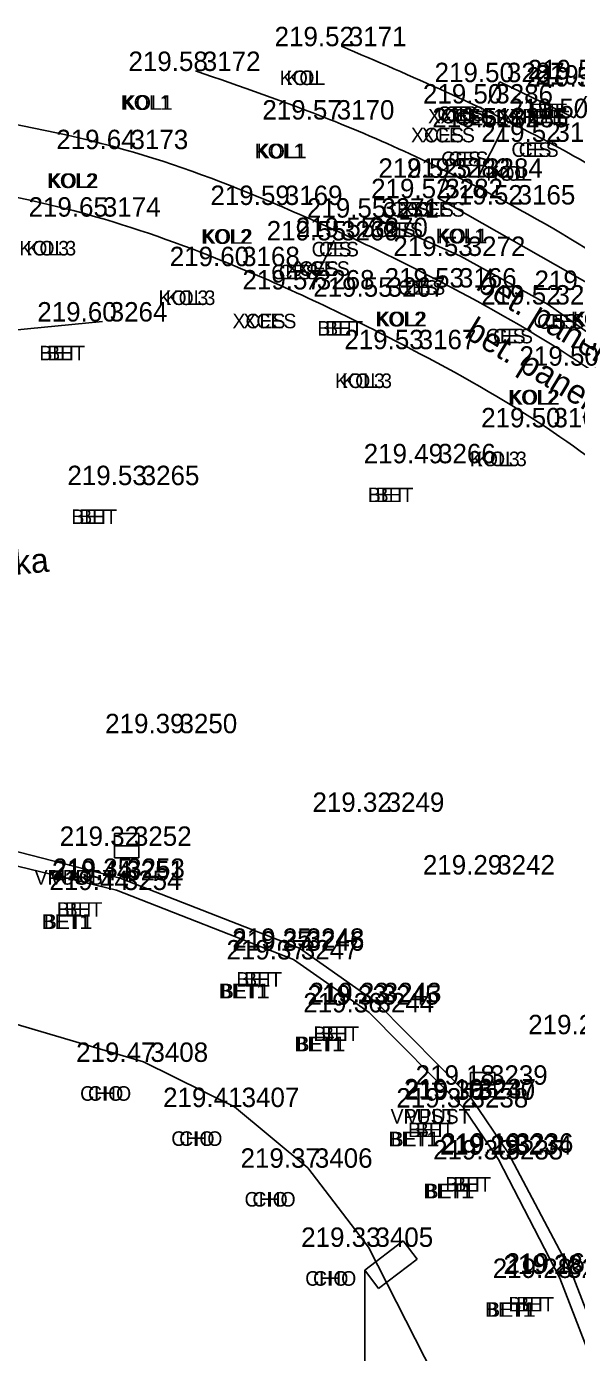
# Model space of a CAD drawing. Extents: x -471047 to -470889, y -1102859 to -1102000.
# Drawn here: x -470949.15 to -470937.81, y -1102032.3 to -1102004.99 of the extents above; entities that cross this region are included whole.
import ezdxf

# ---------------------------------------------------------------- set-up
doc = ezdxf.new("R2010")
doc.units = 0
for name, color, linetype in [('Vrstva 1', 7, 'Continuous'), ('Vrstva 22', 7, 'Continuous'), ('Vrstva 23', 7, 'Continuous'), ('Vrstva 25', 7, 'Continuous'), ('Vrstva 34', 7, 'Continuous'), ('Vrstva 35', 7, 'Continuous'), ('Vrstva 36', 7, 'Continuous'), ('Vrstva 38', 7, 'Continuous'), ('Vrstva 7', 7, 'Continuous'), ('Vrstva 8', 7, 'Continuous')]:
    doc.layers.add(name, color=color, linetype=linetype)

msp = doc.modelspace()

# ---------------------------------------------------------------- linework, layer by layer
at = {"layer": 'Vrstva 1'}
for points in [[(-471040.344, -1102858.385), (-471031.676, -1102846.187), (-471026.357, -1102838.629), (-471023.212, -1102833.975), (-471019.21, -1102827.465), (-471016.861, -1102823.272), (-471013.099, -1102815.912), (-471010.824, -1102810.955), (-471007.329, -1102802.292), (-471005.34, -1102796.515), (-471002.842, -1102787.838), (-471001.3, -1102780.997), (-471000.19, -1102774.713), (-470999.247, -1102768.204), (-470998.794, -1102764.784), (-470997.199, -1102751.812), (-470994.899, -1102732.807), (-470992.551, -1102713.262), (-470990.326, -1102694.887), (-470988.122, -1102676.57), (-470985.812, -1102657.305), (-470983.537, -1102638.407), (-470981.386, -1102620.622), (-470979.843, -1102608.014), (-470976.377, -1102579.253), (-470972.945, -1102550.69), (-470970.475, -1102530.206), (-470967.905, -1102508.801), (-470965.053, -1102485.131), (-470962.734, -1102465.9), (-470960.173, -1102444.812), (-470957.795, -1102425.103), (-470954.965, -1102401.839), (-470953.834, -1102392.574), (-470952.33, -1102379.985), (-470950.744, -1102366.853), (-470948.978, -1102352.106), (-470947.037, -1102335.844), (-470944.949, -1102318.462), (-470944.013, -1102310.745), (-470942.39, -1102297.267), (-470939.519, -1102273.45), (-470937.593, -1102257.43), (-470936.064, -1102244.81), (-470934.114, -1102228.634), (-470931.621, -1102207.856), (-470929.536, -1102190.857), (-470926.572, -1102166.31), (-470924.91, -1102152.663), (-470923.413, -1102140.333), (-470921.923, -1102127.669), (-470921.155, -1102120.084), (-470920.446, -1102109.574), (-470919.912, -1102099.137), (-470919.63, -1102088.981), (-470919.523, -1102081.193), (-470919.563, -1102070.395), (-470919.714, -1102064.236), (-470920.134, -1102054.704), (-470920.462, -1102047.615), (-470920.599, -1102044.52), (-470920.743, -1102041.873), (-470921.125, -1102034.455), (-470921.774, -1102030.337), (-470922.418, -1102027.787), (-470923.734, -1102023.93), (-470924.872, -1102021.434), (-470926.752, -1102018.182), (-470927.953, -1102016.45), (-470929.616, -1102014.424), (-470932.252, -1102011.756), (-470935.111, -1102009.425), (-470938.391, -1102007.371), (-470942.651, -1102005.401)], [(-471041.328, -1102857.18), (-471032.144, -1102844.242), (-471027.583, -1102837.763), (-471024.388, -1102833.028), (-471020.451, -1102826.6), (-471018.089, -1102822.378), (-471014.542, -1102815.445), (-471012.233, -1102810.418), (-471009.247, -1102803.108), (-471006.795, -1102796.098), (-471004.315, -1102787.532), (-471002.782, -1102780.723), (-471001.674, -1102774.458), (-471000.75, -1102768.095), (-471000.28, -1102764.601), (-470998.692, -1102751.741), (-470996.378, -1102732.635), (-470994.028, -1102713.058), (-470991.808, -1102694.749), (-470989.616, -1102676.447), (-470987.284, -1102657.013), (-470985.031, -1102638.272), (-470982.87, -1102620.431), (-470981.334, -1102607.933), (-470977.881, -1102579.263), (-470974.429, -1102550.492), (-470971.964, -1102530.054), (-470969.391, -1102508.607), (-470966.54, -1102484.984), (-470964.231, -1102465.853), (-470961.679, -1102444.752), (-470959.304, -1102425.078), (-470956.455, -1102401.634), (-470955.339, -1102392.489), (-470953.812, -1102379.71), (-470952.249, -1102366.808), (-470950.479, -1102352.023), (-470948.536, -1102335.868), (-470946.426, -1102318.233), (-470945.493, -1102310.531), (-470943.864, -1102297.013), (-470940.984, -1102273.071), (-470939.078, -1102257.195), (-470937.559, -1102244.684), (-470935.592, -1102228.353), (-470933.101, -1102207.653), (-470931.011, -1102190.57), (-470928.046, -1102166.021), (-470926.409, -1102152.578), (-470924.898, -1102140.121), (-470923.427, -1102127.544), (-470922.647, -1102119.826), (-470921.919, -1102109.229), (-470921.42, -1102099.134), (-470921.127, -1102089.016), (-470921.023, -1102081.453), (-470921.061, -1102070.468), (-470921.209, -1102064.314), (-470921.666, -1102053.966), (-470922.156, -1102043.345), (-470922.299, -1102039.934), (-470922.637, -1102034.36), (-470923.091, -1102031.241), (-470923.847, -1102028.247), (-470925.083, -1102024.594), (-470926.222, -1102022.086), (-470928.04, -1102018.943), (-470929.138, -1102017.357), (-470930.929, -1102015.175), (-470933.062, -1102013.049), (-470936.379, -1102010.368), (-470939.169, -1102008.662), (-470942.899, -1102006.906), (-470945.661, -1102005.908)], [(-471043.557, -1102855.955), (-471035.129, -1102844.026), (-471029.872, -1102836.499), (-471026.577, -1102831.578), (-471022.675, -1102825.415), (-471020.123, -1102821.053), (-471016.667, -1102814.59), (-471014.208, -1102809.45), (-471011.177, -1102802.451), (-471008.55, -1102795.333), (-471006.082, -1102787.209), (-471004.464, -1102780.376), (-471003.265, -1102774.167), (-471002.327, -1102767.948), (-471001.636, -1102762.527), (-471000.297, -1102751.605), (-470997.959, -1102732.524), (-470995.602, -1102712.802), (-470993.412, -1102694.623), (-470991.21, -1102676.17), (-470988.891, -1102656.857), (-470986.625, -1102638.083), (-470984.455, -1102620.195), (-470982.936, -1102607.733), (-470979.497, -1102579.223), (-470976.023, -1102550.279), (-470973.554, -1102529.822), (-470970.991, -1102508.497), (-470968.146, -1102484.787), (-470965.835, -1102465.72), (-470963.284, -1102444.529), (-470960.91, -1102424.942), (-470958.043, -1102401.343), (-470956.946, -1102392.356), (-470955.396, -1102379.408), (-470953.851, -1102366.636), (-470952.049, -1102351.733), (-470950.124, -1102335.611), (-470948.034, -1102318.083), (-470947.094, -1102310.328), (-470945.421, -1102296.51), (-470942.58, -1102272.848), (-470940.675, -1102256.948), (-470939.176, -1102244.526), (-470937.187, -1102228.174), (-470934.708, -1102207.467), (-470932.621, -1102190.433), (-470929.634, -1102165.778), (-470928.004, -1102152.415), (-470926.45, -1102139.595), (-470925.003, -1102127.418), (-470924.249, -1102119.695), (-470923.515, -1102109.093), (-470923.018, -1102099.069), (-470922.711, -1102088.911), (-470922.643, -1102081.356), (-470922.797, -1102070.414), (-470923.018, -1102064.454), (-470923.52, -1102053.203), (-470923.823, -1102047.529), (-470924.123, -1102041.506), (-470924.462, -1102037.486), (-470924.934, -1102031.904), (-470925.664, -1102028.672), (-470926.771, -1102025.506), (-470927.959, -1102022.914), (-470929.674, -1102020.028), (-470930.76, -1102018.498), (-470932.447, -1102016.478), (-470935.215, -1102013.816), (-470937.644, -1102011.98), (-470940.381, -1102010.371), (-470943.968, -1102008.669), (-470947.145, -1102007.524), (-470950.874, -1102006.74)], [(-471044.756, -1102855.056), (-471036.376, -1102843.177), (-471031.167, -1102835.741), (-471027.859, -1102830.8), (-471023.934, -1102824.593), (-471021.43, -1102820.312), (-471018.011, -1102813.91), (-471015.536, -1102808.75), (-471012.578, -1102801.897), (-471009.95, -1102794.77), (-471007.561, -1102786.914), (-471005.936, -1102780.074), (-471004.727, -1102773.818), (-471003.828, -1102767.827), (-471003.121, -1102762.345), (-471001.787, -1102751.467), (-470999.446, -1102732.348), (-470997.073, -1102712.539), (-470994.902, -1102694.521), (-470992.696, -1102676.023), (-470990.376, -1102656.68), (-470988.131, -1102638.071), (-470985.947, -1102620.018), (-470984.417, -1102607.512), (-470980.993, -1102579.08), (-470977.514, -1102550.137), (-470975.048, -1102529.649), (-470972.488, -1102508.37), (-470969.618, -1102484.508), (-470967.34, -1102465.669), (-470964.767, -1102444.39), (-470962.402, -1102424.781), (-470959.534, -1102401.193), (-470958.432, -1102392.151), (-470956.883, -1102379.208), (-470955.335, -1102366.424), (-470953.535, -1102351.506), (-470951.606, -1102335.399), (-470949.519, -1102317.94), (-470948.575, -1102310.159), (-470946.889, -1102296.144), (-470944.056, -1102272.618), (-470942.139, -1102256.659), (-470940.657, -1102244.341), (-470938.638, -1102227.749), (-470936.19, -1102207.298), (-470934.102, -1102190.255), (-470931.124, -1102165.639), (-470929.492, -1102152.254), (-470927.915, -1102139.252), (-470926.46, -1102127.103), (-470925.74, -1102119.604), (-470925.012, -1102108.913), (-470924.523, -1102099.054), (-470924.217, -1102088.866), (-470924.148, -1102081.334), (-470924.301, -1102070.391), (-470924.518, -1102064.43), (-470924.97, -1102054.435), (-470925.588, -1102041.569), (-470925.963, -1102035.313), (-470926.405, -1102032.225), (-470927.078, -1102029.198), (-470928.123, -1102026.148), (-470929.318, -1102023.558), (-470930.84, -1102020.97), (-470931.868, -1102019.515), (-470933.443, -1102017.605), (-470936.26, -1102014.885), (-470938.429, -1102013.255), (-470941.213, -1102011.639), (-470944.847, -1102009.927), (-470947.723, -1102008.912), (-470951.444, -1102008.161), (-470954.511, -1102007.931), (-470957.895, -1102008.041)]]:
    msp.add_spline(points, degree=3, dxfattribs=at)
at = {"layer": 'Vrstva 23'}
for p, q in [((-470941.379, -1102030.003), (-470942.174, -1102030.608)), ((-470941.089, -1102030.38), (-470941.379, -1102030.003)), ((-470942.174, -1102030.608), (-470942.174, -1102033.108)), ((-470942.174, -1102030.608), (-470941.886, -1102030.986)), ((-470941.886, -1102030.986), (-470941.089, -1102030.38))]:
    msp.add_line(p, q, dxfattribs=at)
at = {"layer": 'Vrstva 25'}
for p, q in [((-470947.331, -1102021.617), (-470947.331, -1102022.117)), ((-470946.831, -1102021.617), (-470947.331, -1102021.617)), ((-470946.831, -1102022.117), (-470946.831, -1102021.617)), ((-470947.331, -1102021.867), (-470946.831, -1102021.867)), ((-470947.331, -1102022.117), (-470946.831, -1102022.117)), ((-470939.992, -1102026.539), (-470939.992, -1102027.039)), ((-470939.492, -1102026.539), (-470939.992, -1102026.539)), ((-470939.992, -1102026.789), (-470939.492, -1102026.789)), ((-470939.492, -1102027.039), (-470939.492, -1102026.539)), ((-470939.992, -1102027.039), (-470939.492, -1102027.039))]:
    msp.add_line(p, q, dxfattribs=at)
at = {"layer": 'Vrstva 34'}
for p, q in [((-470942.65, -1102005.4), (-470942.65, -1102005.4)), ((-470945.66, -1102005.91), (-470945.66, -1102005.91)), ((-470939.39, -1102006.14), (-470939.39, -1102006.14)), ((-470939.63, -1102006.58), (-470939.63, -1102006.58)), ((-470942.9, -1102006.91), (-470942.9, -1102006.91)), ((-470939.31, -1102007.07), (-470939.31, -1102007.07)), ((-470937.86, -1102006.88), (-470937.86, -1102006.88)), ((-470938.39, -1102007.37), (-470938.39, -1102007.37)), ((-470947.15, -1102007.52), (-470947.15, -1102007.52)), ((-470940.51, -1102008.11), (-470940.51, -1102008.11)), ((-470939.84, -1102008.11), (-470939.84, -1102008.11)), ((-470943.97, -1102008.67), (-470943.97, -1102008.67)), ((-470940.66, -1102008.53), (-470940.66, -1102008.53)), ((-470939.17, -1102008.66), (-470939.17, -1102008.66)), ((-470947.72, -1102008.91), (-470947.72, -1102008.91)), ((-470941.98, -1102008.93), (-470941.98, -1102008.93)), ((-470942.81, -1102009.4), (-470942.81, -1102009.4)), ((-470942.21, -1102009.33), (-470942.21, -1102009.33)), ((-470940.2, -1102009.72), (-470940.2, -1102009.72)), ((-470944.85, -1102009.93), (-470944.85, -1102009.93)), ((-470943.31, -1102010.41), (-470943.31, -1102010.41)), ((-470940.38, -1102010.37), (-470940.38, -1102010.37)), ((-470941.85, -1102010.56), (-470941.85, -1102010.56)), ((-470938.39, -1102010.72), (-470938.39, -1102010.72)), ((-470947.58, -1102011.07), (-470947.58, -1102011.07)), ((-470941.21, -1102011.64), (-470941.21, -1102011.64)), ((-470938.43, -1102013.25), (-470938.43, -1102013.25)), ((-470940.81, -1102013.99), (-470940.81, -1102013.99)), ((-470946.92, -1102014.44), (-470946.92, -1102014.44)), ((-470946.14, -1102019.55), (-470946.14, -1102019.55)), ((-470941.87, -1102021.17), (-470941.87, -1102021.17)), ((-470947.08, -1102021.87), (-470947.08, -1102021.87)), ((-470947.24, -1102022.58), (-470947.24, -1102022.58)), ((-470947.22, -1102022.53), (-470947.22, -1102022.53)), ((-470939.59, -1102022.46), (-470939.59, -1102022.46)), ((-470947.29, -1102022.78), (-470947.29, -1102022.78)), ((-470943.52, -1102023.97), (-470943.52, -1102023.97)), ((-470943.52, -1102024.03), (-470943.52, -1102024.03)), ((-470943.64, -1102024.21), (-470943.64, -1102024.21)), ((-470941.97, -1102025.14), (-470941.97, -1102025.14)), ((-470941.93, -1102025.09), (-470941.93, -1102025.09)), ((-470942.08, -1102025.3), (-470942.08, -1102025.3)), ((-470946.74, -1102026.32), (-470946.74, -1102026.32)), ((-470939.74, -1102026.79), (-470939.74, -1102026.79)), ((-470939.98, -1102027.07), (-470939.98, -1102027.07)), ((-470944.86, -1102027.25), (-470944.86, -1102027.25)), ((-470940.14, -1102027.26), (-470940.14, -1102027.26)), ((-470940, -1102027.1), (-470940, -1102027.1)), ((-470939.42, -1102028.33), (-470939.42, -1102028.33)), ((-470939.24, -1102028.23), (-470939.24, -1102028.23)), ((-470939.21, -1102028.19), (-470939.21, -1102028.19)), ((-470943.35, -1102028.5), (-470943.35, -1102028.5)), ((-470942.1, -1102030.13), (-470942.1, -1102030.13)), ((-470938.15, -1102030.77), (-470938.15, -1102030.77)), ((-470937.93, -1102030.69), (-470937.93, -1102030.69)), ((-470937.91, -1102030.66), (-470937.91, -1102030.66))]:
    msp.add_line(p, q, dxfattribs=at)
at = {"layer": 'Vrstva 7'}
for p, q in [((-470947.292, -1102022.781), (-470951.249, -1102021.828)), ((-470943.642, -1102024.212), (-470947.292, -1102022.781)), ((-470942.08, -1102025.3), (-470943.642, -1102024.212)), ((-470940.138, -1102027.264), (-470942.08, -1102025.3)), ((-470939.417, -1102028.328), (-470940.138, -1102027.264)), ((-470938.149, -1102030.773), (-470939.417, -1102028.328)), ((-470936.415, -1102035.276), (-470938.149, -1102030.773))]:
    msp.add_line(p, q, dxfattribs=at)
at = {"layer": 'Vrstva 8'}
for p, q in [((-470939.629, -1102006.58), (-470939.391, -1102006.135)), ((-470939.391, -1102006.135), (-470937.857, -1102006.875)), ((-470937.857, -1102006.875), (-470937.496, -1102006.231)), ((-470939.84, -1102008.112), (-470939.309, -1102007.068)), ((-470940.656, -1102008.531), (-470940.509, -1102008.106)), ((-470937.333, -1102010.417), (-470940.656, -1102008.531)), ((-470942.206, -1102009.332), (-470941.983, -1102008.931)), ((-470941.983, -1102008.931), (-470940.2, -1102009.722)), ((-470943.311, -1102010.414), (-470942.806, -1102009.401)), ((-470940.2, -1102009.722), (-470938.394, -1102010.719)), ((-470938.394, -1102010.719), (-470935.102, -1102013.056)), ((-470956.214, -1102011.908), (-470947.582, -1102011.072)), ((-470947.215, -1102022.532), (-470951.173, -1102021.523)), ((-470943.521, -1102023.974), (-470947.215, -1102022.532)), ((-470941.934, -1102025.091), (-470943.521, -1102023.974)), ((-470939.978, -1102027.068), (-470941.934, -1102025.091)), ((-470946.736, -1102026.317), (-470950.493, -1102025.212)), ((-470944.86, -1102027.248), (-470946.736, -1102026.317)), ((-470939.214, -1102028.193), (-470939.978, -1102027.068)), ((-470943.348, -1102028.5), (-470944.86, -1102027.248)), ((-470937.909, -1102030.66), (-470939.214, -1102028.193)), ((-470942.096, -1102030.133), (-470943.348, -1102028.5)), ((-470940.746, -1102032.778), (-470942.096, -1102030.133)), ((-470936.167, -1102035.17), (-470937.909, -1102030.66))]:
    msp.add_line(p, q, dxfattribs=at)

# ---------------------------------------------------------------- texts
at = {"layer": 'Vrstva 22'}
for s, rotation, p in [('bet. panely', 328.7683, (-470939.903, -1102010.396)), ('bet. panely', 328.7683, (-470940.141, -1102011.383)), ('živičná vozovka', 5.5318, (-470953.328, -1102016.672))]:
    msp.add_text(s, height=0.5, rotation=rotation, dxfattribs=at).set_placement(p)
at = {"layer": 'Vrstva 35'}
for s, p in [('KOL', (-470943.925, -1102006.2)), ('KOL', (-470943.789, -1102006.2)), ('KOL1', (-470947.202, -1102006.71)), ('KOL1', (-470947.16, -1102006.71)), ('FIE', (-470938.758, -1102006.88)), ('FIE', (-470938.609, -1102006.88)), ('XCES1 XFIE1', (-470940.87, -1102006.99)), ('CES', (-470940.679, -1102006.94)), ('XCES1 XFIE1', (-470940.612, -1102006.99)), ('CES', (-470940.529, -1102006.94)), ('CES XFIE', (-470940.288, -1102007.03)), ('CES XFIE', (-470939.764, -1102007.03)), ('XCES', (-470941.219, -1102007.38)), ('XCES', (-470940.994, -1102007.38)), ('KOL1', (-470944.442, -1102007.71)), ('KOL1', (-470944.4, -1102007.71)), ('CES', (-470939.149, -1102007.68)), ('CES', (-470938.999, -1102007.68)), ('CES', (-470940.599, -1102007.87)), ('CES', (-470940.449, -1102007.87)), ('KOL', (-470939.665, -1102008.17)), ('KOL', (-470939.529, -1102008.17)), ('KOL2', (-470948.725, -1102008.32)), ('KOL2', (-470948.691, -1102008.32)), ('CES', (-470941.799, -1102008.91)), ('CES', (-470941.649, -1102008.91)), ('XCES', (-470941.429, -1102008.91)), ('XCES', (-470941.204, -1102008.91)), ('CES', (-470941.949, -1102009.33)), ('CES', (-470941.799, -1102009.33)), ('KOL2', (-470945.545, -1102009.47)), ('KOL2', (-470945.511, -1102009.47)), ('KOL1', (-470940.712, -1102009.46)), ('KOL1', (-470940.67, -1102009.46)), ('KOL3', (-470949.295, -1102009.71)), ('KOL3', (-470949.148, -1102009.71)), ('CES', (-470943.269, -1102009.73)), ('CES', (-470943.119, -1102009.73)), ('XCES', (-470943.799, -1102010.13)), ('XCES', (-470943.574, -1102010.13)), ('CES', (-470944.099, -1102010.2)), ('CES', (-470943.949, -1102010.2)), ('CES', (-470941.489, -1102010.52)), ('CES', (-470941.339, -1102010.52)), ('KOL3', (-470946.425, -1102010.73)), ('KOL3', (-470946.278, -1102010.73)), ('XCES', (-470944.899, -1102011.21)), ('XCES', (-470944.674, -1102011.21)), ('KOL2', (-470941.955, -1102011.17)), ('KOL2', (-470941.921, -1102011.17)), ('CES', (-470938.619, -1102011.22)), ('CES', (-470938.469, -1102011.22)), ('KOL1', (-470937.922, -1102011.17)), ('KOL1', (-470937.88, -1102011.17)), ('BET', (-470943.15, -1102011.36)), ('BET', (-470942.989, -1102011.36)), ('CES', (-470939.679, -1102011.52)), ('CES', (-470939.529, -1102011.52)), ('BET', (-470948.88, -1102011.87)), ('BET', (-470948.719, -1102011.87)), ('KOL3', (-470942.785, -1102012.44)), ('KOL3', (-470942.638, -1102012.44)), ('KOL2', (-470939.215, -1102012.78)), ('KOL2', (-470939.181, -1102012.78)), ('KOL3', (-470940.005, -1102014.05)), ('KOL3', (-470939.858, -1102014.05)), ('BET', (-470942.11, -1102014.79)), ('BET', (-470941.949, -1102014.79)), ('BET', (-470948.22, -1102015.24)), ('BET', (-470948.059, -1102015.24)), ('VPUST', (-470948.98, -1102022.67)), ('VPUST', (-470948.669, -1102022.67)), ('BET', (-470948.52, -1102023.33)), ('BET', (-470948.359, -1102023.33)), ('BET1', (-470948.832, -1102023.58)), ('BET1', (-470948.79, -1102023.58)), ('BET', (-470944.82, -1102024.77)), ('BET', (-470944.659, -1102024.77)), ('BET1', (-470945.182, -1102025.01)), ('BET1', (-470945.14, -1102025.01)), ('BET', (-470943.23, -1102025.89)), ('BET', (-470943.069, -1102025.89)), ('BET1', (-470943.622, -1102026.1)), ('BET1', (-470943.58, -1102026.1)), ('CHO', (-470948.041, -1102027.12)), ('CHO', (-470947.879, -1102027.12)), ('VPUST', (-470941.64, -1102027.59)), ('VPUST', (-470941.329, -1102027.59)), ('BET', (-470941.28, -1102027.87)), ('BET', (-470941.119, -1102027.87)), ('CHO', (-470946.161, -1102028.05)), ('CHO', (-470945.999, -1102028.05)), ('BET1', (-470941.682, -1102028.06)), ('BET1', (-470941.64, -1102028.06)), ('BET', (-470940.51, -1102028.99)), ('BET', (-470940.349, -1102028.99)), ('BET1', (-470940.962, -1102029.13)), ('BET1', (-470940.92, -1102029.13)), ('CHO', (-470944.651, -1102029.3)), ('CHO', (-470944.489, -1102029.3)), ('CHO', (-470943.401, -1102030.93)), ('CHO', (-470943.239, -1102030.93)), ('BET', (-470939.21, -1102031.46)), ('BET', (-470939.049, -1102031.46)), ('BET1', (-470939.692, -1102031.57)), ('BET1', (-470939.65, -1102031.57))]:
    msp.add_text(s, height=0.3, dxfattribs=at).set_placement(p)
at = {"layer": 'Vrstva 36'}
for s, p in [(' 3171', (-470942.65, -1102005.4)), (' 3172', (-470945.66, -1102005.91)), (' 3287', (-470939.39, -1102006.14)), (' 3286', (-470939.63, -1102006.58)), (' 3170', (-470942.9, -1102006.91)), (' 3285', (-470939.31, -1102007.07)), (' 3173', (-470947.15, -1102007.52)), (' 3164', (-470938.39, -1102007.37)), (' 3283', (-470940.51, -1102008.11)), (' 3284', (-470939.84, -1102008.11)), (' 3282', (-470940.66, -1102008.53)), (' 3174', (-470947.72, -1102008.91)), (' 3169', (-470943.97, -1102008.67)), (' 3165', (-470939.17, -1102008.66)), (' 3271', (-470941.98, -1102008.93)), (' 3269', (-470942.81, -1102009.4)), (' 3270', (-470942.21, -1102009.33)), (' 3272', (-470940.2, -1102009.72)), (' 3168', (-470944.85, -1102009.93)), (' 3268', (-470943.31, -1102010.41)), (' 3166', (-470940.38, -1102010.37)), (' 3267', (-470941.85, -1102010.56)), (' 3273', (-470938.39, -1102010.72)), (' 3264', (-470947.58, -1102011.07)), (' 3167', (-470941.21, -1102011.64)), (' 3160', (-470938.43, -1102013.25)), (' 3266', (-470940.81, -1102013.99)), (' 3265', (-470946.92, -1102014.44)), (' 3250', (-470946.14, -1102019.55)), (' 3249', (-470941.87, -1102021.17)), (' 3252', (-470947.08, -1102021.87)), (' 3253', (-470947.22, -1102022.53)), (' 3242', (-470939.59, -1102022.46)), (' 3254', (-470947.29, -1102022.78)), (' 3251', (-470947.24, -1102022.58)), (' 3248', (-470943.52, -1102023.97)), (' 3246', (-470943.52, -1102024.03)), (' 3247', (-470943.64, -1102024.21)), (' 3244', (-470942.08, -1102025.3)), (' 3245', (-470941.97, -1102025.14)), (' 3243', (-470941.93, -1102025.09)), (' 3408', (-470946.74, -1102026.32)), (' 3239', (-470939.74, -1102026.79)), (' 3240', (-470940, -1102027.1)), (' 3237', (-470939.98, -1102027.07)), (' 3407', (-470944.86, -1102027.25)), (' 3238', (-470940.14, -1102027.26)), (' 3234', (-470939.24, -1102028.23)), (' 3236', (-470939.21, -1102028.19)), (' 3406', (-470943.35, -1102028.5)), (' 3235', (-470939.42, -1102028.33)), (' 3405', (-470942.1, -1102030.13)), (' 3232', (-470938.15, -1102030.77))]:
    msp.add_text(s, height=0.4, dxfattribs=at).set_placement(p)
at = {"layer": 'Vrstva 38'}
for s, p in [('219.52 ', (-470944.031, -1102005.4)), ('219.58 ', (-470947.044, -1102005.91)), ('219.50 ', (-470940.733, -1102006.14)), ('219.50 ', (-470938.813, -1102006.08)), ('219.50 ', (-470938.843, -1102006.23)), ('219.58 ', (-470938.654, -1102006.19)), ('219.50 ', (-470940.973, -1102006.58)), ('219.57 ', (-470944.283, -1102006.91)), ('219.50 ', (-470939.203, -1102006.88)), ('219.51 ', (-470940.78, -1102007.07)), ('219.64 ', (-470948.532, -1102007.52)), ('219.52 ', (-470939.771, -1102007.37)), ('219.52 ', (-470941.891, -1102008.11)), ('219.51 ', (-470941.31, -1102008.11)), ('219.52 ', (-470942.041, -1102008.53)), ('219.65 ', (-470949.104, -1102008.91)), ('219.59 ', (-470945.354, -1102008.67)), ('219.52 ', (-470940.551, -1102008.66)), ('219.55 ', (-470943.364, -1102008.93)), ('219.55 ', (-470944.194, -1102009.4)), ('219.55 ', (-470943.594, -1102009.33)), ('219.53 ', (-470941.583, -1102009.72)), ('219.60 ', (-470946.193, -1102009.93)), ('219.57 ', (-470944.693, -1102010.41)), ('219.53 ', (-470941.763, -1102010.37)), ('219.50 ', (-470938.673, -1102010.42)), ('219.55 ', (-470943.234, -1102010.56)), ('219.52 ', (-470939.771, -1102010.72)), ('219.60 ', (-470948.923, -1102011.07)), ('219.53 ', (-470942.593, -1102011.64)), ('219.50 ', (-470938.983, -1102011.98)), ('219.50 ', (-470939.773, -1102013.25)), ('219.49 ', (-470942.194, -1102013.99)), ('219.53 ', (-470948.303, -1102014.44)), ('219.39 ', (-470947.524, -1102019.55)), ('219.32 ', (-470943.251, -1102021.17)), ('219.32 ', (-470948.461, -1102021.87)), ('219.35 ', (-470948.604, -1102022.53)), ('219.29 ', (-470940.974, -1102022.46)), ('219.44 ', (-470948.672, -1102022.78)), ('219.44 ', (-470948.622, -1102022.58)), ('219.25 ', (-470944.904, -1102023.97)), ('219.37 ', (-470944.903, -1102024.03)), ('219.37 ', (-470945.023, -1102024.21)), ('219.36 ', (-470943.44, -1102025.3)), ('219.33 ', (-470943.353, -1102025.14)), ('219.23 ', (-470943.313, -1102025.09)), ('219.23 ', (-470938.803, -1102025.75)), ('219.47 ', (-470948.123, -1102026.32)), ('219.18 ', (-470941.124, -1102026.79)), ('219.19 ', (-470941.364, -1102027.07)), ('219.30 ', (-470941.343, -1102027.1)), ('219.41 ', (-470946.33, -1102027.25)), ('219.32 ', (-470941.521, -1102027.26)), ('219.29 ', (-470940.624, -1102028.23)), ('219.19 ', (-470940.594, -1102028.19)), ('219.37 ', (-470944.733, -1102028.5)), ('219.30 ', (-470940.763, -1102028.33)), ('219.33 ', (-470943.483, -1102030.13)), ('219.28 ', (-470939.314, -1102030.69)), ('219.16 ', (-470939.27, -1102030.66)), ('219.28 ', (-470939.534, -1102030.77))]:
    msp.add_text(s, height=0.4, dxfattribs=at).set_placement(p)

doc.saveas('drawing.dxf')
